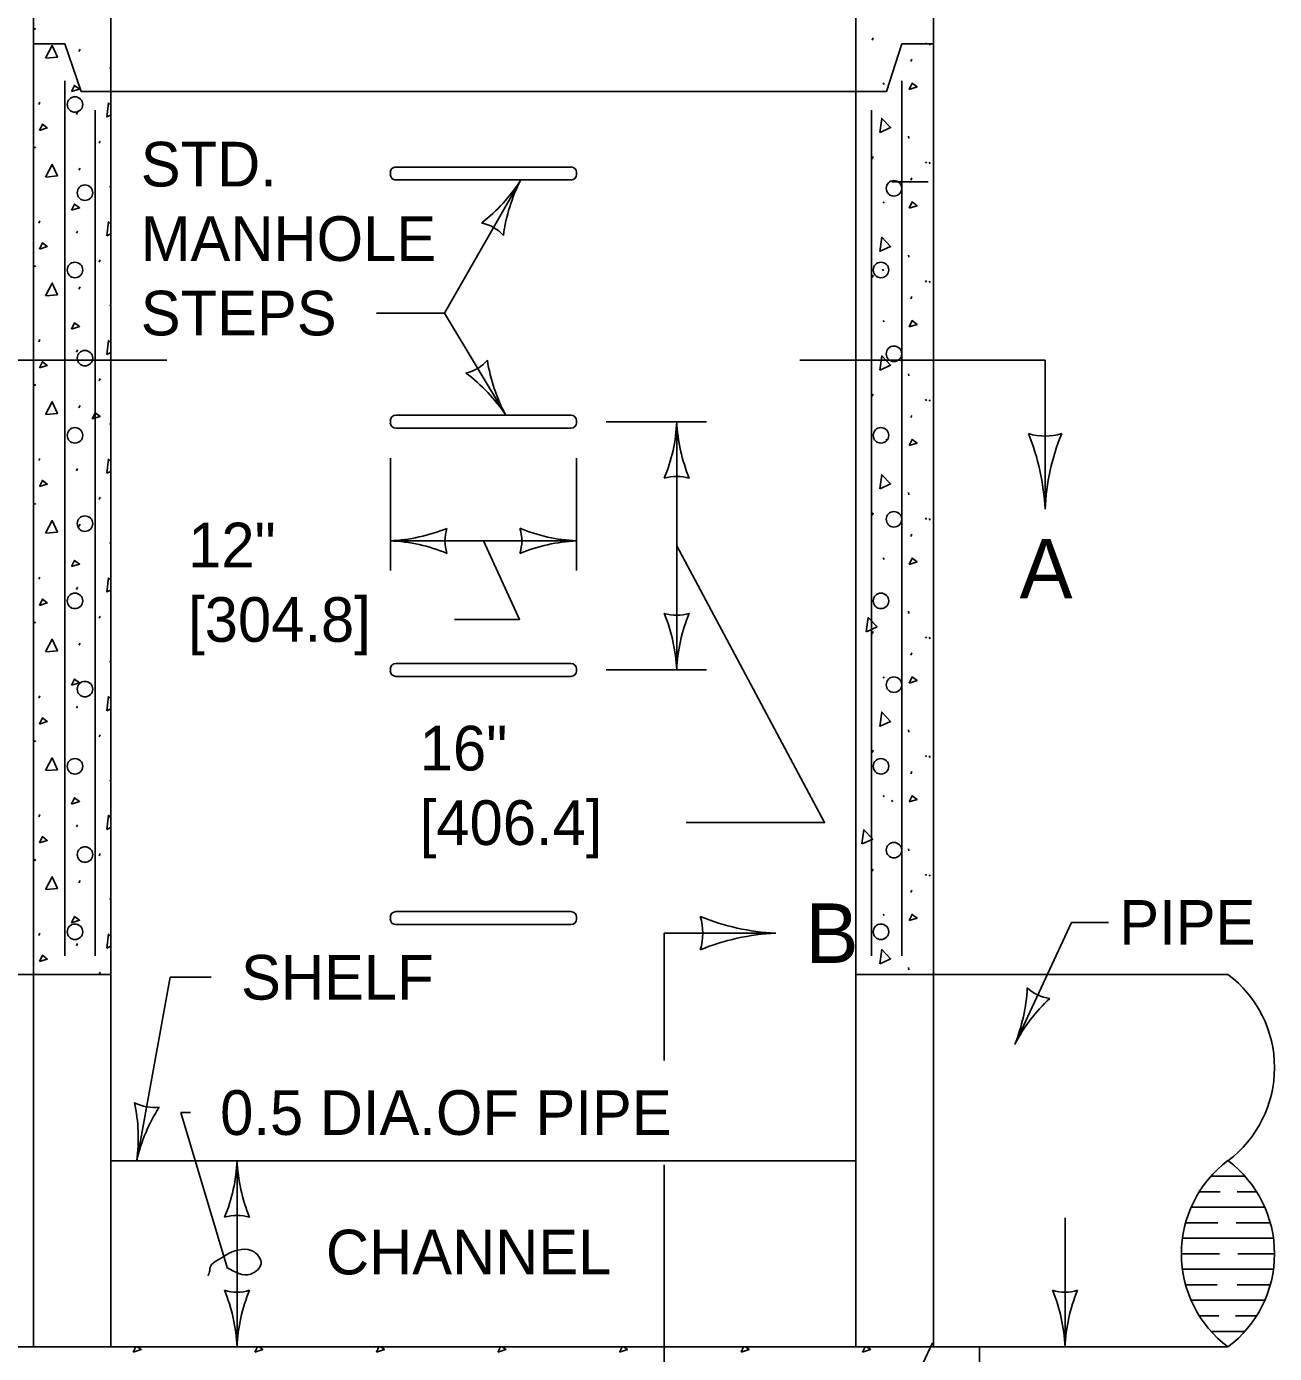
# Model space of a CAD drawing. Extents: x 49991.4 to 50028.3, y 49987.6 to 50011.4.
# Drawn here: x 50007.274 to 50008.951, y 49995.28 to 49997.062 of the extents above; entities that cross this region are included whole.
import ezdxf

# ---------------------------------------------------------------- set-up
doc = ezdxf.new("R2010")
doc.units = 0
for name, color, linetype in [('Level 1', 7, 'Continuous'), ('Level 2', 7, 'Continuous'), ('Level 3', 7, 'Continuous'), ('Level 4', 7, 'Continuous'), ('Level 6', 7, 'Continuous')]:
    doc.layers.add(name, color=color, linetype=linetype)

msp = doc.modelspace()

# ---------------------------------------------------------------- linework, layer by layer
at = {"layer": 'Level 1'}
for p, q in [((50007.2835, 49997.143), (50007.2835, 49995.7888)), ((50007.3877, 49997.143), (50007.3877, 49995.2888)), ((50008.3883, 49997.143), (50008.3883, 49995.2888)), ((50008.4924, 49997.143), (50008.4924, 49995.7888)), ((50007.2852, 49997.0599), (50007.2866, 49997.0579)), ((50007.3259, 49997.0388), (50007.2835, 49997.0388)), ((50007.3259, 49997.0388), (50007.3478, 49996.9745)), ((50008.4102, 49997.0437), (50008.4115, 49997.0467)), ((50008.4501, 49997.0388), (50008.4296, 49996.9745)), ((50008.4501, 49997.0388), (50008.4924, 49997.0388)), ((50008.4818, 49997.0398), (50008.4831, 49997.0378)), ((50008.4868, 49997.039), (50008.4882, 49997.037)), ((50007.3448, 49997.0283), (50007.3462, 49997.0313)), ((50008.4621, 49997.0151), (50008.4634, 49997.0181)), ((50007.3864, 49997.007), (50007.3877, 49997.0052)), ((50007.3259, 49995.8138), (50007.3259, 49996.9888)), ((50008.4248, 49996.9861), (50008.4261, 49996.9841)), ((50008.4501, 49995.8138), (50008.4501, 49996.9888)), ((50007.3478, 49996.9745), (50008.4296, 49996.9745)), ((50007.2909, 49996.9574), (50007.2922, 49996.9604)), ((50007.3665, 49995.8138), (50007.3665, 49996.9495)), ((50008.4094, 49995.8138), (50008.4094, 49996.9495)), ((50007.3415, 49996.9437), (50007.3428, 49996.9467)), ((50008.459, 49996.9145), (50008.4594, 49996.9115)), ((50007.2852, 49996.9004), (50007.2866, 49996.8984)), ((50007.3718, 49996.9051), (50007.3731, 49996.9081)), ((50008.4102, 49996.8842), (50008.4115, 49996.8872)), ((50008.4818, 49996.8803), (50008.4831, 49996.8783)), ((50008.4868, 49996.8796), (50008.4882, 49996.8776)), ((50007.3448, 49996.8688), (50007.3462, 49996.8718)), ((50007.763, 49996.8658), (50007.763, 49996.8632)), ((50008.0056, 49996.8732), (50007.7704, 49996.8732)), ((50008.013, 49996.8632), (50008.013, 49996.8658)), ((50008.4621, 49996.8556), (50008.4634, 49996.8586)), ((50007.3864, 49996.8475), (50007.3877, 49996.8457)), ((50007.7704, 49996.8558), (50008.0056, 49996.8558)), ((50008.4365, 49996.8535), (50008.4854, 49996.8535)), ((50008.4248, 49996.8266), (50008.4261, 49996.8246)), ((50007.2909, 49996.7979), (50007.2922, 49996.8009)), ((50007.3415, 49996.7842), (50007.3428, 49996.7872)), ((50008.459, 49996.755), (50008.4594, 49996.752)), ((50007.2852, 49996.741), (50007.2866, 49996.739)), ((50007.3718, 49996.7456), (50007.3731, 49996.7486)), ((50008.4241, 49996.7359), (50008.4254, 49996.7339)), ((50008.4102, 49996.7248), (50008.4115, 49996.7278)), ((50008.4818, 49996.7208), (50008.4831, 49996.7188)), ((50008.4868, 49996.7201), (50008.4882, 49996.7181)), ((50007.3448, 49996.7094), (50007.3462, 49996.7124)), ((50008.4621, 49996.6962), (50008.4634, 49996.6992)), ((50007.3864, 49996.6881), (50007.3877, 49996.6862)), ((50008.4248, 49996.6672), (50008.4261, 49996.6652)), ((50007.2909, 49996.6384), (50007.2922, 49996.6414)), ((50007.3415, 49996.6248), (50007.3428, 49996.6278)), ((50008.459, 49996.5956), (50008.4594, 49996.5926)), ((50007.2852, 49996.5815), (50007.2866, 49996.5795)), ((50007.3718, 49996.5862), (50007.3731, 49996.5892)), ((50008.4102, 49996.5653), (50008.4115, 49996.5683)), ((50008.4818, 49996.5614), (50008.4831, 49996.5594)), ((50008.4868, 49996.5606), (50008.4882, 49996.5586)), ((50007.3448, 49996.5499), (50007.3462, 49996.5529)), ((50008.0056, 49996.5399), (50007.7704, 49996.5399)), ((50008.4621, 49996.5367), (50008.4634, 49996.5397)), ((50007.3864, 49996.5286), (50007.3877, 49996.5268)), ((50007.763, 49996.5325), (50007.763, 49996.5298)), ((50007.7704, 49996.5224), (50008.0056, 49996.5224)), ((50008.0131, 49996.5298), (50008.0131, 49996.5325)), ((50008.4289, 49996.5078), (50008.4302, 49996.5058)), ((50007.2909, 49996.479), (50007.2922, 49996.482)), ((50007.3415, 49996.4654), (50007.3428, 49996.4684)), ((50008.459, 49996.4361), (50008.4594, 49996.4331)), ((50007.2852, 49996.422), (50007.2866, 49996.42)), ((50007.3718, 49996.4267), (50007.3731, 49996.4297)), ((50008.4102, 49996.4058), (50008.4115, 49996.4088)), ((50008.4818, 49996.402), (50008.4831, 49996.4)), ((50008.4868, 49996.4012), (50008.4882, 49996.3992)), ((50007.3448, 49996.3905), (50007.3462, 49996.3935)), ((50008.4621, 49996.3772), (50008.4634, 49996.3802)), ((50007.3864, 49996.3692), (50007.3877, 49996.3674)), ((50008.4248, 49996.3483), (50008.4261, 49996.3463)), ((50007.2909, 49996.3196), (50007.2922, 49996.3226)), ((50007.3415, 49996.3059), (50007.3428, 49996.3089)), ((50007.3718, 49996.2673), (50007.3731, 49996.2702)), ((50008.459, 49996.2766), (50008.4594, 49996.2736)), ((50007.2852, 49996.2626), (50007.2866, 49996.2606)), ((50007.3448, 49996.231), (50007.3462, 49996.234)), ((50008.4102, 49996.2464), (50008.4115, 49996.2494)), ((50008.4818, 49996.2425), (50008.4831, 49996.2405)), ((50008.4868, 49996.2417), (50008.4882, 49996.2397)), ((50008.4621, 49996.2178), (50008.4634, 49996.2208)), ((50007.3864, 49996.2097), (50007.3877, 49996.2079)), ((50007.763, 49996.1992), (50007.763, 49996.1965)), ((50008.0056, 49996.2066), (50007.7704, 49996.2066)), ((50008.013, 49996.1965), (50008.013, 49996.1992)), ((50007.7704, 49996.1891), (50008.0056, 49996.1891)), ((50008.4248, 49996.1888), (50008.4261, 49996.1868)), ((50007.2909, 49996.1601), (50007.2922, 49996.1631)), ((50007.3415, 49996.1464), (50007.3428, 49996.1494)), ((50007.3718, 49996.1078), (50007.3731, 49996.1108)), ((50008.459, 49996.1172), (50008.4594, 49996.1142)), ((50007.2852, 49996.1032), (50007.2866, 49996.1012)), ((50008.4102, 49996.0869), (50008.4115, 49996.0899)), ((50008.4818, 49996.083), (50008.4831, 49996.081)), ((50008.4868, 49996.0823), (50008.4882, 49996.0803)), ((50008.4621, 49996.0584), (50008.4634, 49996.0614)), ((50007.3864, 49996.0502), (50007.3877, 49996.0484)), ((50008.4248, 49996.0294), (50008.4261, 49996.0274)), ((50008.4364, 49996.0228), (50008.4377, 49996.0208)), ((50007.2909, 49996.0006), (50007.2922, 49996.0036)), ((50007.3415, 49995.987), (50007.3428, 49995.99)), ((50007.3718, 49995.9484), (50007.3731, 49995.9514)), ((50008.459, 49995.9578), (50008.4594, 49995.9548)), ((50007.2852, 49995.9437), (50007.2866, 49995.9417)), ((50007.3448, 49995.9121), (50007.3462, 49995.9151)), ((50008.4102, 49995.9275), (50008.4115, 49995.9305)), ((50008.4818, 49995.9236), (50008.4831, 49995.9216)), ((50008.4868, 49995.9228), (50008.4882, 49995.9208)), ((50008.4621, 49995.8989), (50008.4634, 49995.9019)), ((50007.3864, 49995.8908), (50007.3877, 49995.889)), ((50007.763, 49995.8658), (50007.763, 49995.8632)), ((50008.0056, 49995.8733), (50007.7704, 49995.8733)), ((50008.013, 49995.8632), (50008.013, 49995.8658)), ((50008.4248, 49995.8699), (50008.4261, 49995.8679)), ((50007.2909, 49995.8412), (50007.2922, 49995.8442)), ((50007.7704, 49995.8558), (50008.0056, 49995.8558)), ((50007.3415, 49995.8275), (50007.3428, 49995.8305)), ((50006.4889, 49995.7888), (50007.3877, 49995.7888)), ((50007.3718, 49995.7889), (50007.3731, 49995.7919)), ((50008.3883, 49995.7888), (50008.888, 49995.7888)), ((50008.459, 49995.7983), (50008.4594, 49995.7953)), ((50007.3877, 49995.5388), (50008.3883, 49995.5388)), ((50008.9107, 49995.518), (50008.8653, 49995.518)), ((50008.8778, 49995.4971), (50008.8496, 49995.4971)), ((50008.9264, 49995.4971), (50008.9003, 49995.4971)), ((50008.9374, 49995.4763), (50008.8385, 49995.4763)), ((50008.8746, 49995.4554), (50008.8312, 49995.4554)), ((50008.9448, 49995.4554), (50008.8992, 49995.4554)), ((50008.9491, 49995.4346), (50008.8269, 49995.4346)), ((50008.8768, 49995.4138), (50008.8255, 49995.4138)), ((50008.9505, 49995.4138), (50008.9014, 49995.4138)), ((50008.9491, 49995.393), (50008.8269, 49995.393)), ((50008.8736, 49995.3721), (50008.8312, 49995.3721)), ((50008.9448, 49995.3721), (50008.9003, 49995.3721)), ((50008.9374, 49995.3513), (50008.8385, 49995.3513)), ((50008.8758, 49995.3304), (50008.8496, 49995.3304)), ((50008.9264, 49995.3304), (50008.8982, 49995.3304)), ((50008.9107, 49995.3096), (50008.8653, 49995.3096)), ((50006.4889, 49995.2888), (50008.888, 49995.2888)), ((50007.384, 49995.2888), (50007.3841, 49995.2885)), ((50007.5472, 49995.2888), (50007.5474, 49995.2885)), ((50007.7105, 49995.2888), (50007.7106, 49995.2885)), ((50007.8738, 49995.2888), (50007.8739, 49995.2885)), ((50008.037, 49995.2888), (50008.0372, 49995.2885)), ((50008.1301, 49995.2888), (50008.1302, 49995.2885)), ((50008.3636, 49995.2888), (50008.3637, 49995.2885)), ((50008.5268, 49995.2888), (50008.527, 49995.2885)), ((50008.5543, 49995.1638), (50008.5543, 49995.2888))]:
    msp.add_line(p, q, dxfattribs=at)
for points in [[(50007.2999, 49997.0193), (50007.3089, 49997.0363), (50007.3158, 49997.0206), (50007.3002, 49997.0193)], [(50007.3349, 49996.9745), (50007.3389, 49996.9828), (50007.3456, 49996.9778), (50007.3349, 49996.9745)], [(50008.4598, 49996.9774), (50008.4638, 49996.9858), (50008.4704, 49996.9808), (50008.4598, 49996.9774)], [(50007.382, 49996.9403), (50007.3846, 49996.9593), (50007.3877, 49996.9562)], [(50007.2916, 49996.9224), (50007.2956, 49996.9307), (50007.3022, 49996.9257), (50007.2916, 49996.9224)], [(50007.3877, 49996.9428), (50007.3823, 49996.9404)], [(50008.4204, 49996.9194), (50008.423, 49996.9384), (50008.4349, 49996.9261), (50008.4207, 49996.9195)], [(50007.2999, 49996.8598), (50007.3089, 49996.8768), (50007.3158, 49996.8612), (50007.3002, 49996.8598)], [(50007.3349, 49996.8151), (50007.3389, 49996.8234), (50007.3456, 49996.8184), (50007.3349, 49996.8151)], [(50008.4598, 49996.818), (50008.4638, 49996.8263), (50008.4704, 49996.8213), (50008.4598, 49996.818)], [(50007.382, 49996.7808), (50007.3846, 49996.7998), (50007.3877, 49996.7967)], [(50007.2916, 49996.763), (50007.2956, 49996.7713), (50007.3022, 49996.7663), (50007.2916, 49996.763)], [(50007.3877, 49996.7834), (50007.3823, 49996.7809)], [(50008.4204, 49996.7599), (50008.423, 49996.779), (50008.4349, 49996.7666), (50008.4207, 49996.76)], [(50007.2999, 49996.7004), (50007.3089, 49996.7174), (50007.3158, 49996.7017), (50007.3002, 49996.7004)], [(50007.3349, 49996.6556), (50007.3389, 49996.6639), (50007.3456, 49996.659), (50007.3349, 49996.6556)], [(50008.4598, 49996.6586), (50008.4638, 49996.6669), (50008.4704, 49996.6619), (50008.4598, 49996.6586)], [(50007.382, 49996.6214), (50007.3846, 49996.6404), (50007.3877, 49996.6373)], [(50007.2916, 49996.6035), (50007.2956, 49996.6118), (50007.3022, 49996.6068), (50007.2916, 49996.6035)], [(50007.3877, 49996.624), (50007.3823, 49996.6215)], [(50008.4204, 49996.6005), (50008.423, 49996.6195), (50008.4349, 49996.6072), (50008.4207, 49996.6006)], [(50007.2999, 49996.541), (50007.3089, 49996.5579), (50007.3158, 49996.5423), (50007.3002, 49996.541)], [(50007.3626, 49996.535), (50007.3666, 49996.5433), (50007.3732, 49996.5383), (50007.3626, 49996.535)], [(50008.4598, 49996.4991), (50008.4638, 49996.5074), (50008.4704, 49996.5024), (50008.4598, 49996.4991)], [(50007.382, 49996.4619), (50007.3846, 49996.4809), (50007.3877, 49996.4778)], [(50007.2916, 49996.444), (50007.2956, 49996.4524), (50007.3022, 49996.4474), (50007.2916, 49996.444)], [(50007.3877, 49996.4645), (50007.3823, 49996.462)], [(50008.4204, 49996.441), (50008.423, 49996.46), (50008.4349, 49996.4478), (50008.4207, 49996.4412)], [(50007.2999, 49996.3815), (50007.3089, 49996.3985), (50007.3158, 49996.3828), (50007.3002, 49996.3815)], [(50007.3349, 49996.3367), (50007.3389, 49996.345), (50007.3456, 49996.34), (50007.3349, 49996.3367)], [(50008.4598, 49996.3396), (50008.4638, 49996.348), (50008.4704, 49996.343), (50008.4598, 49996.3396)], [(50007.382, 49996.3024), (50007.3846, 49996.3215), (50007.3877, 49996.3184)], [(50007.2916, 49996.2846), (50007.2956, 49996.2929), (50007.3022, 49996.2879), (50007.2916, 49996.2846)], [(50007.3877, 49996.305), (50007.3823, 49996.3026)], [(50008.4022, 49996.2491), (50008.4049, 49996.2681), (50008.4168, 49996.2558), (50008.4026, 49996.2492)], [(50007.2999, 49996.222), (50007.3089, 49996.239), (50007.3158, 49996.2234), (50007.3002, 49996.222)], [(50007.3349, 49996.1772), (50007.3389, 49996.1856), (50007.3456, 49996.1806), (50007.3349, 49996.1772)], [(50008.4598, 49996.1802), (50008.4638, 49996.1885), (50008.4704, 49996.1835), (50008.4598, 49996.1802)], [(50007.382, 49996.143), (50007.3846, 49996.162), (50007.3877, 49996.1589)], [(50007.3877, 49996.1456), (50007.3823, 49996.1431)], [(50007.2916, 49996.1251), (50007.2956, 49996.1334), (50007.3022, 49996.1284), (50007.2916, 49996.1251)], [(50008.4204, 49996.1221), (50008.423, 49996.1412), (50008.4349, 49996.1288), (50008.4207, 49996.1222)], [(50007.2999, 49996.0626), (50007.3089, 49996.0796), (50007.3158, 49996.0639), (50007.3002, 49996.0626)], [(50007.3349, 49996.0178), (50007.3389, 49996.0261), (50007.3456, 49996.0211), (50007.3349, 49996.0178)], [(50008.4598, 49996.0207), (50008.4638, 49996.029), (50008.4704, 49996.024), (50008.4598, 49996.0207)], [(50007.382, 49995.9835), (50007.3846, 49996.0026), (50007.3877, 49995.9994)], [(50007.3877, 49995.9861), (50007.3823, 49995.9836)], [(50007.2916, 49995.9657), (50007.2956, 49995.974), (50007.3022, 49995.969), (50007.2916, 49995.9657)], [(50008.3964, 49995.9641), (50008.3991, 49995.9832), (50008.411, 49995.9708), (50008.3968, 49995.9642)], [(50007.2999, 49995.9031), (50007.3089, 49995.9201), (50007.3158, 49995.9044), (50007.3002, 49995.9031)], [(50007.3349, 49995.8583), (50007.3389, 49995.8666), (50007.3456, 49995.8617), (50007.3349, 49995.8583)], [(50008.4598, 49995.8612), (50008.4638, 49995.8696), (50008.4704, 49995.8646), (50008.4598, 49995.8612)], [(50007.382, 49995.8241), (50007.3846, 49995.8431), (50007.3877, 49995.84)], [(50007.3877, 49995.8267), (50007.3823, 49995.8242)], [(50007.2916, 49995.8062), (50007.2956, 49995.8146), (50007.3022, 49995.8096), (50007.2916, 49995.8062)], [(50008.4204, 49995.8032), (50008.423, 49995.8222), (50008.4349, 49995.8099), (50008.4207, 49995.8033)], [(50008.4913, 49995.2941), (50008.4781, 49995.2664), (50008.4848, 49995.2614), (50008.4741, 49995.258)], [(50007.4178, 49995.2818), (50007.4211, 49995.2888)], [(50007.4236, 49995.2888), (50007.4284, 49995.2852), (50007.4178, 49995.2818)], [(50007.581, 49995.2818), (50007.5844, 49995.2888)], [(50007.5869, 49995.2888), (50007.5917, 49995.2852), (50007.581, 49995.2818)], [(50007.7443, 49995.2818), (50007.7476, 49995.2888)], [(50007.7502, 49995.2888), (50007.755, 49995.2852), (50007.7443, 49995.2818)], [(50007.9076, 49995.2818), (50007.9109, 49995.2888)], [(50007.9134, 49995.2888), (50007.9182, 49995.2852), (50007.9076, 49995.2818)], [(50008.0708, 49995.2818), (50008.0742, 49995.2888)], [(50008.0767, 49995.2888), (50008.0815, 49995.2852), (50008.0708, 49995.2818)], [(50008.2341, 49995.2818), (50008.2374, 49995.2888)], [(50008.24, 49995.2888), (50008.2448, 49995.2852), (50008.2341, 49995.2818)], [(50008.3974, 49995.2818), (50008.4007, 49995.2888)], [(50008.4032, 49995.2888), (50008.408, 49995.2852), (50008.3974, 49995.2818)]]:
    msp.add_lwpolyline(points, dxfattribs=at)
for centre in [(50007.3394, 49996.9572), (50007.3528, 49996.8387), (50008.4394, 49996.8446), (50007.3394, 49996.735), (50008.422, 49996.735), (50007.3528, 49996.6165), (50008.4394, 49996.6224), (50007.3394, 49996.5128), (50008.422, 49996.5128), (50007.3528, 49996.3943), (50008.4394, 49996.4002), (50007.3394, 49996.2906), (50008.422, 49996.2906), (50007.3528, 49996.1721), (50008.4394, 49996.178), (50007.3394, 49996.0684), (50008.422, 49996.0684), (50007.3528, 49995.9499), (50008.4394, 49995.9558), (50007.3394, 49995.8462), (50008.422, 49995.8462)]:
    msp.add_circle(centre, 0.0104, dxfattribs=at)
for centre, radius, start, end in [((50007.7704, 49996.8659), 0.00742, 90, 180), ((50007.7704, 49996.8632), 0.00742, 180, 270), ((50008.0056, 49996.8659), 0.00742, 0, 90), ((50008.0056, 49996.8632), 0.00742, 270, 0), ((50007.7704, 49996.5325), 0.00742, 90, 180), ((50008.0056, 49996.5325), 0.00742, 0, 90), ((50007.7704, 49996.5299), 0.00742, 180, 270), ((50008.0056, 49996.5299), 0.00742, 270, 0), ((50007.7704, 49996.1992), 0.00742, 90, 180), ((50008.0056, 49996.1992), 0.00742, 0, 90), ((50007.7704, 49996.1966), 0.00742, 180, 270), ((50008.0056, 49996.1966), 0.00742, 270, 0), ((50007.7704, 49995.8659), 0.00742, 90, 180), ((50007.7704, 49995.8632), 0.00742, 180, 270), ((50008.0056, 49995.8659), 0.00742, 0, 90), ((50008.0056, 49995.8632), 0.00742, 270, 0), ((50008.7943, 49995.6638), 0.1563, 306.8699, 53.1301), ((50008.9818, 49995.4138), 0.1563, 126.8699, 233.1301), ((50008.7943, 49995.4138), 0.1563, 306.8699, 53.1301)]:
    msp.add_arc(centre, radius, start, end, dxfattribs=at)
at = {"layer": 'Level 3'}
for p, q in [((50007.8356, 49996.6771), (50007.9381, 49996.8558)), ((50007.7446, 49996.6771), (50007.8356, 49996.6771)), ((50007.8356, 49996.6771), (50007.9182, 49996.5399)), ((50008.0531, 49996.5312), (50008.1877, 49996.5312)), ((50008.1477, 49996.5312), (50008.1477, 49996.1978)), ((50007.763, 49996.4824), (50007.763, 49996.3312)), ((50008.013, 49996.4824), (50008.013, 49996.3312)), ((50007.763, 49996.3712), (50008.013, 49996.3712)), ((50008.053, 49996.1978), (50008.1877, 49996.1978)), ((50008.6016, 49995.6948), (50008.6777, 49995.8588)), ((50008.7277, 49995.8588), (50008.6777, 49995.8588)), ((50007.4674, 49995.7851), (50007.4224, 49995.5388)), ((50007.5225, 49995.7851), (50007.4674, 49995.7851)), ((50007.4944, 49995.6034), (50007.4815, 49995.6034)), ((50007.5439, 49995.3953), (50007.4815, 49995.6034)), ((50007.5571, 49995.2888), (50007.5571, 49995.5388)), ((50008.6693, 49995.2888), (50008.6693, 49995.4622))]:
    msp.add_line(p, q, dxfattribs=at)
for points in [[(50007.888, 49996.3712), (50007.9365, 49996.2656), (50007.8493, 49996.2656)], [(50008.1477, 49996.3645), (50008.3463, 49995.9928), (50008.1604, 49995.9928)]]:
    msp.add_lwpolyline(points, dxfattribs=at)
for centre, radius, start, end in [((50007.75, 49996.9743), 0.2223, 307.618, 327.8015), ((50008.1457, 49996.75), 0.233, 152.9893, 172.2391), ((50007.8743, 49996.7446), 0.0548, 42.3008, 78.0232), ((50007.8521, 49996.6498), 0.0548, 283.1885, 318.9108), ((50008.1132, 49996.6467), 0.2223, 188.5057, 208.6892), ((50007.7248, 49996.4101), 0.233, 33.877, 53.1268), ((50007.9256, 49996.5404), 0.2223, 337.456, 357.6395), ((50008.3804, 49996.5427), 0.233, 182.8273, 202.0772), ((50008.6424, 49996.5848), 0.073, 252.1388, 287.8612), ((50008.3321, 49996.3985), 0.3107, 2.8273, 22.0772), ((50008.9386, 49996.4016), 0.2964, 157.456, 177.6395), ((50008.1477, 49996.403), 0.0548, 72.1388, 107.8612), ((50007.7515, 49996.6039), 0.233, 272.8273, 292.0772), ((50007.8912, 49996.3712), 0.0548, 162.1388, 197.8612), ((50008.0222, 49996.5934), 0.2223, 247.456, 267.6395), ((50007.8848, 49996.3712), 0.0548, 342.1388, 17.8612), ((50007.7539, 49996.1491), 0.2223, 67.456, 87.6395), ((50008.0245, 49996.1385), 0.233, 92.8273, 112.0772), ((50008.1477, 49996.326), 0.0548, 252.1388, 287.8612), ((50007.915, 49996.1863), 0.233, 2.8273, 22.0772), ((50008.3698, 49996.1887), 0.2223, 157.456, 177.6395), ((50008.2928, 49996.1406), 0.2964, 247.456, 267.6395), ((50008.1097, 49995.8444), 0.073, 342.1388, 17.8612), ((50008.2959, 49995.5341), 0.3107, 92.8273, 112.0772), ((50008.3857, 49995.7822), 0.233, 337.969, 357.2189), ((50008.6555, 49995.8111), 0.0548, 227.2805, 263.0029), ((50008.7993, 49995.5931), 0.2223, 132.5977, 152.7812), ((50007.4455, 49995.665), 0.0548, 241.7849, 277.5072), ((50007.1914, 49995.5694), 0.233, 352.4733, 11.7232), ((50007.6393, 49995.4899), 0.2223, 147.102, 167.2856), ((50007.335, 49995.548), 0.2223, 337.456, 357.6395), ((50007.7898, 49995.5503), 0.233, 182.8273, 202.0772), ((50007.5571, 49995.4106), 0.0548, 72.1388, 107.8612), ((50007.5571, 49995.417), 0.0548, 252.1388, 287.8612), ((50007.3244, 49995.2773), 0.233, 2.8273, 22.0772), ((50007.7792, 49995.2797), 0.2223, 157.456, 177.6395), ((50008.6693, 49995.417), 0.0548, 252.1388, 287.8612), ((50008.4366, 49995.2773), 0.233, 2.8273, 22.0772), ((50008.8914, 49995.2797), 0.2223, 157.456, 177.6395)]:
    msp.add_arc(centre, radius, start, end, dxfattribs=at)
msp.add_spline([(50007.5433, 49995.3955), (50007.5756, 49995.3866), (50007.5893, 49995.4003), (50007.5801, 49995.4163), (50007.5457, 49995.414), (50007.5342, 49995.4072), (50007.5204, 49995.3934), (50007.5204, 49995.3911), (50007.5181, 49995.3843)], degree=3, dxfattribs=at)
at = {"layer": 'Level 4'}
for p, q in [((50007.2835, 49995.2888), (50007.2835, 49995.7888)), ((50008.4924, 49995.2888), (50008.4924, 49995.7888))]:
    msp.add_line(p, q, dxfattribs=at)
at = {"layer": 'Level 6'}
for p, q in [((50007.463, 49996.6138), (50007.1335, 49996.6138)), ((50008.313, 49996.6138), (50008.6424, 49996.6138)), ((50008.6424, 49996.6138), (50008.6424, 49996.4138)), ((50008.1306, 49995.8444), (50008.2806, 49995.8444)), ((50008.1306, 49995.8444), (50008.1306, 49995.6734)), ((50008.1306, 49995.5334), (50008.1306, 49995.0138))]:
    msp.add_line(p, q, dxfattribs=at)

# ---------------------------------------------------------------- texts
at = {"layer": 'Level 2'}
for s, height, p in [('STD.', 0.06, (50007.4278, 49996.8471)), ('MANHOLE', 0.06, (50007.4278, 49996.7471)), ('STEPS', 0.06, (50007.4278, 49996.6471)), ('12"', 0.06, (50007.4914, 49996.3356)), ('A', 0.0799, (50008.6081, 49996.2939)), ('[304.8]', 0.06, (50007.4914, 49996.2356)), ('16"', 0.06, (50007.8025, 49996.0628)), ('[406.4]', 0.06, (50007.8025, 49995.9628)), ('B', 0.0799, (50008.3206, 49995.8044)), ('PIPE', 0.06, (50008.7421, 49995.8288)), ('SHELF', 0.06, (50007.5625, 49995.7551)), ('0.5 DIA.OF PIPE', 0.06, (50007.5344, 49995.5734)), ('CHANNEL', 0.06, (50007.6765, 49995.3861))]:
    msp.add_text(s, height=height, dxfattribs=at).set_placement(p)

doc.saveas('drawing.dxf')
